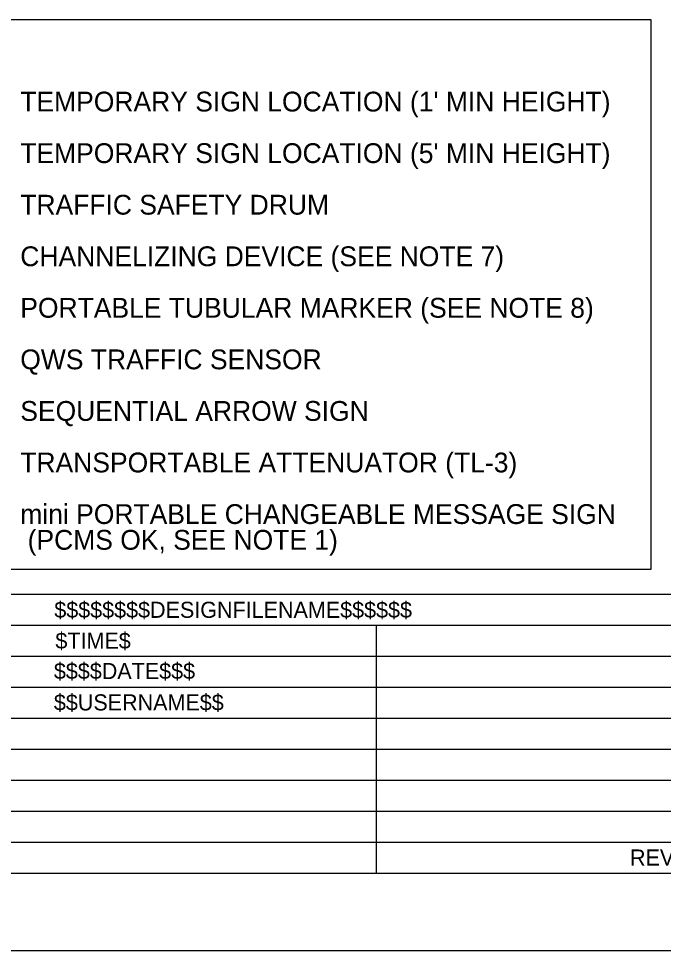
# Model space of a CAD drawing. Extents: x 99958 to 100176, y 99935 to 100011.
# Drawn here: x 100020.733 to 100023.34, y 99939.687 to 99943.451 of the extents above; entities that cross this region are included whole.
import ezdxf

# ---------------------------------------------------------------- set-up
doc = ezdxf.new("R2010")
doc.units = 0
for name, color, linetype in [('SH_GI_PlotLimits', 7, 'Continuous'), ('SH_GI_SheetBorder', 7, 'Continuous'), ('SH_GI_SheetTextInCells', 7, 'Continuous'), ('SH_GI_TitleBlockText', 7, 'Continuous'), ('TR_WZ_WorkZoneTextCurrent', 7, 'Continuous')]:
    doc.layers.add(name, color=color, linetype=linetype)

msp = doc.modelspace()

# ---------------------------------------------------------------- linework, layer by layer
at = {"layer": 'SH_GI_PlotLimits'}
msp.add_lwpolyline([(100019.0625, 99939.6875), (100036.0625, 99939.6875), (100036.0625, 99950.6875), (100019.0625, 99950.6875)], close=True, dxfattribs=at)
at = {"layer": 'SH_GI_SheetBorder'}
for p, q in [((100020, 99941.1259), (100035.75, 99941.1259)), ((100020, 99941.0008), (100027.4566, 99941.0008)), ((100022.179, 99941.0008), (100022.179, 99940)), ((100020, 99940.8757), (100022.1821, 99940.8757)), ((100022.1821, 99940.8757), (100025.4466, 99940.8757)), ((100020, 99940.7506), (100022.1821, 99940.7506)), ((100022.1821, 99940.7506), (100025.4466, 99940.7506)), ((100020, 99940.6255), (100025.4466, 99940.6255)), ((100020, 99940.5004), (100025.4466, 99940.5004)), ((100020, 99940.3753), (100025.4466, 99940.3753)), ((100020, 99940.2502), (100025.4466, 99940.2502)), ((100020, 99940.1251), (100025.4466, 99940.1251)), ((100020, 99940), (100035.75, 99940))]:
    msp.add_line(p, q, dxfattribs=at)
at = {"layer": 'TR_WZ_WorkZoneTextCurrent'}
msp.add_lwpolyline([(100020.1, 99943.4476), (100023.2886, 99943.4476), (100023.2886, 99941.2259), (100020.1, 99941.2259)], close=True, dxfattribs=at)
msp.add_lwpolyline([(100020.1, 99943.4476), (100023.2886, 99943.4476), (100023.2886, 99941.2259), (100020.1, 99941.2259)], close=True, dxfattribs=at)

# ---------------------------------------------------------------- texts
at = {"layer": 'SH_GI_SheetTextInCells'}
msp.add_text('REVISION', height=0.06505, dxfattribs=at).set_placement((100023.2048, 99940.03))
at = {"layer": 'SH_GI_TitleBlockText'}
for s, height, p in [('$$$$$$$$DESIGNFILENAME$$$$$$', 0.065052, (100020.8775, 99941.0308)), ('$TIME$', 0.06505, (100020.882, 99940.9059)), ('$$$$DATE$$$', 0.065052, (100020.8759, 99940.7835)), ('$$USERNAME$$', 0.065052, (100020.8759, 99940.6567))]:
    msp.add_text(s, height=height, dxfattribs=at).set_placement(p)
at = {"layer": 'TR_WZ_WorkZoneTextCurrent'}
for s, p in [("TEMPORARY SIGN LOCATION (1' MIN HEIGHT)", (100020.74, 99943.0763)), ("TEMPORARY SIGN LOCATION (1' MIN HEIGHT)", (100020.74, 99943.0763)), ("TEMPORARY SIGN LOCATION (5' MIN HEIGHT)", (100020.74, 99942.868)), ("TEMPORARY SIGN LOCATION (5' MIN HEIGHT)", (100020.74, 99942.868)), ('TRAFFIC SAFETY DRUM', (100020.74, 99942.6597)), ('TRAFFIC SAFETY DRUM', (100020.74, 99942.6597)), ('CHANNELIZING DEVICE (SEE NOTE 7)', (100020.74, 99942.4514)), ('CHANNELIZING DEVICE (SEE NOTE 7)', (100020.74, 99942.4514)), ('PORTABLE TUBULAR MARKER (SEE NOTE 8)', (100020.74, 99942.2432)), ('PORTABLE TUBULAR MARKER (SEE NOTE 8)', (100020.74, 99942.2432)), ('QWS TRAFFIC SENSOR', (100020.74, 99942.0349)), ('QWS TRAFFIC SENSOR', (100020.74, 99942.0349)), ('SEQUENTIAL ARROW SIGN', (100020.74, 99941.8266)), ('SEQUENTIAL ARROW SIGN', (100020.74, 99941.8266)), ('TRANSPORTABLE ATTENUATOR (TL-3)', (100020.74, 99941.6183)), ('TRANSPORTABLE ATTENUATOR (TL-3)', (100020.74, 99941.6183)), ('mini PORTABLE CHANGEABLE MESSAGE SIGN', (100020.74, 99941.41)), ('mini PORTABLE CHANGEABLE MESSAGE SIGN', (100020.74, 99941.41)), (' (PCMS OK, SEE NOTE 1)', (100020.74, 99941.3059)), (' (PCMS OK, SEE NOTE 1)', (100020.74, 99941.3059))]:
    msp.add_text(s, height=0.08, rotation=360, dxfattribs=at).set_placement(p)

doc.saveas('drawing.dxf')
